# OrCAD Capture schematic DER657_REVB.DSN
size Custom
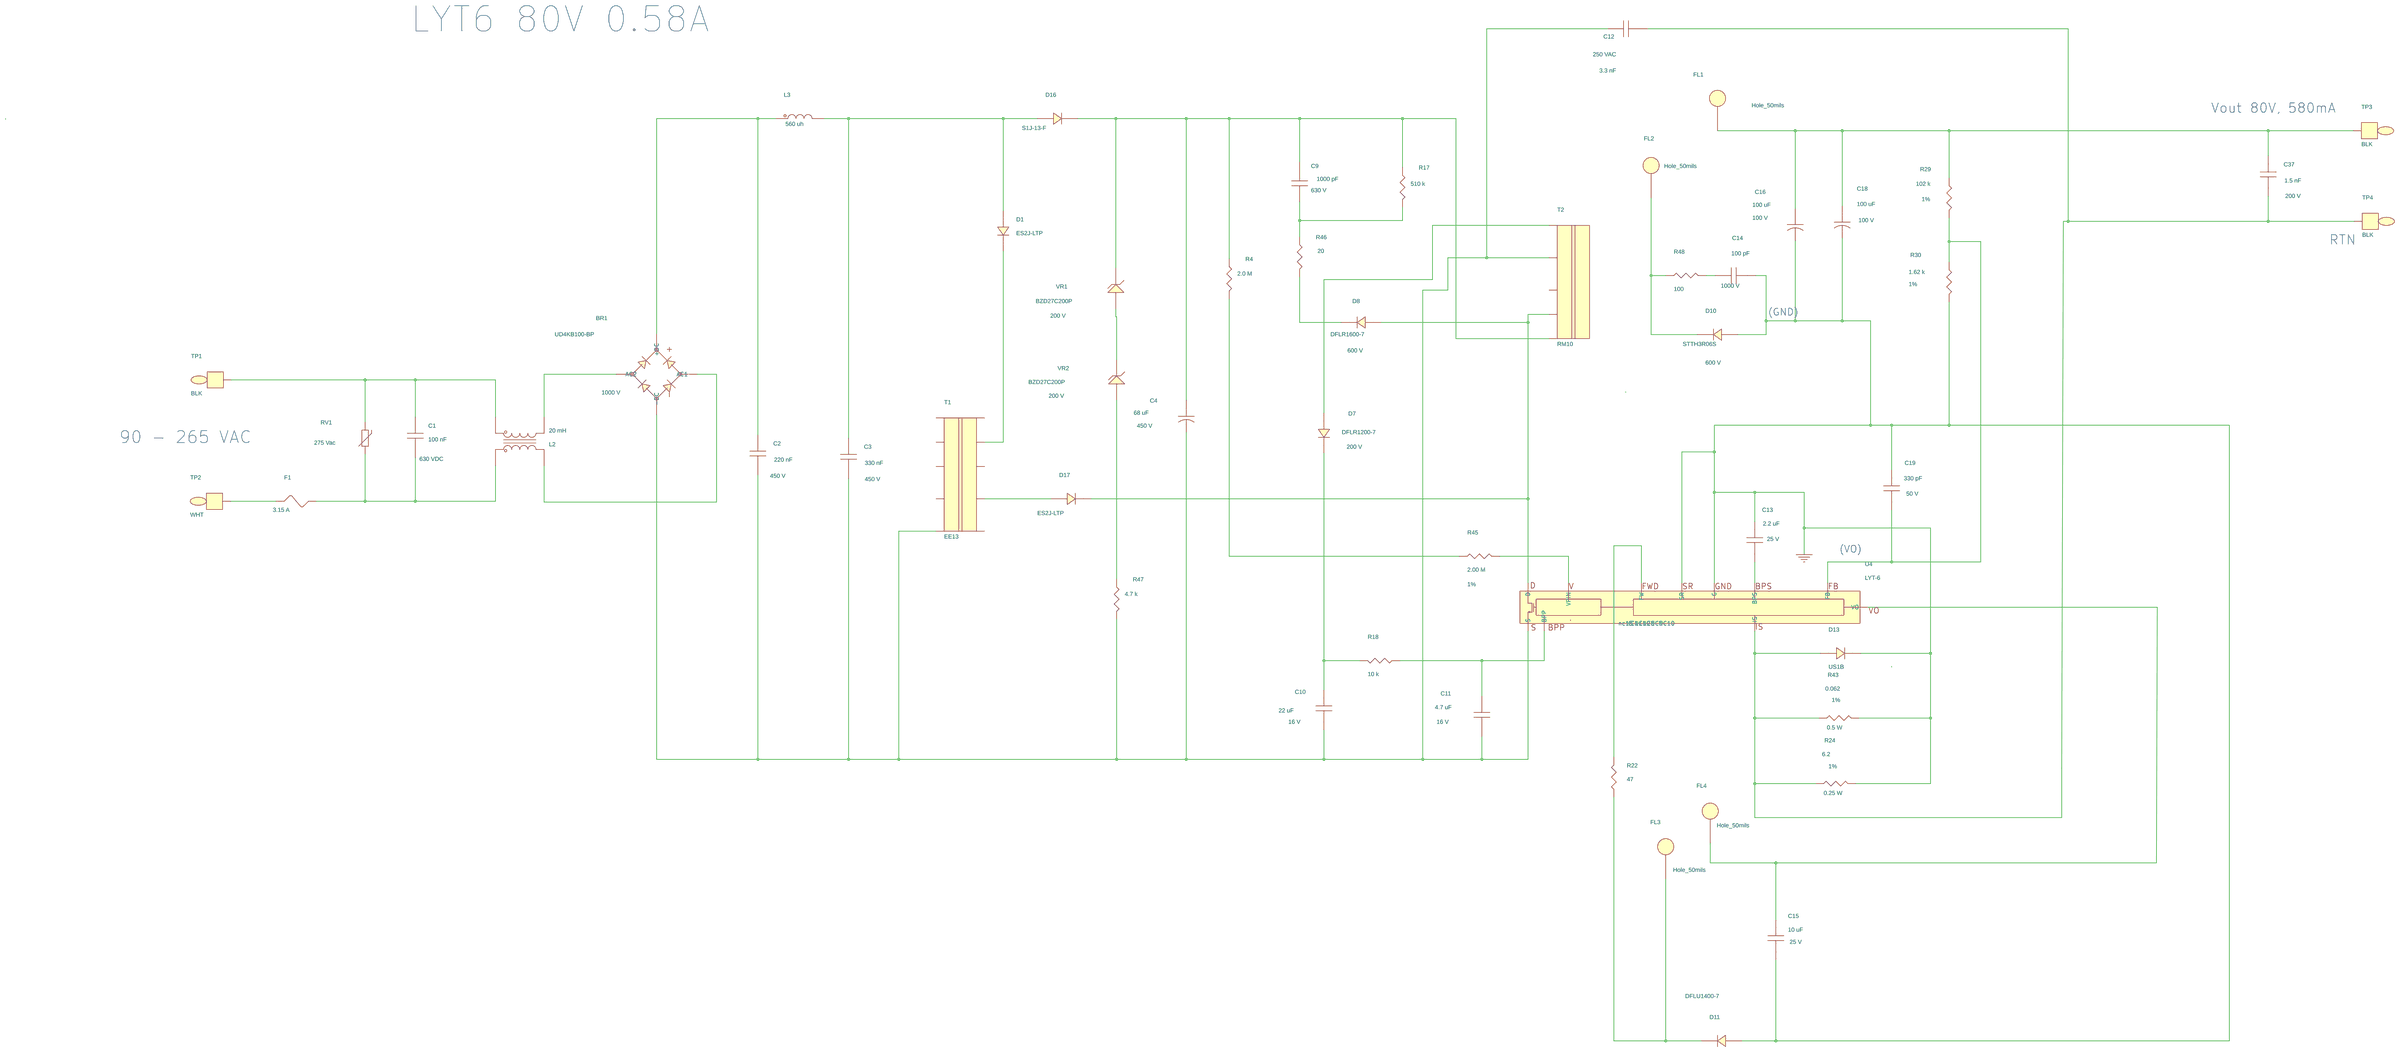
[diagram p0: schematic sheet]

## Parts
BR1  UD4KB100-BP  [pidaxbridgeD3K]
C1  100 nF  [pi_np_cap492x236ls394d040]
C2  220 nF  [pi_np_cap_rad470x220ls400d40]
C3  330 nF  [pi_np_caprad512x299ls394d040]
C4  68 uF  [pipolcapclyd630ls300040]
C9  1000 pF  [pismc1206]
C10  22 uF  [pismc1206]
C11  4.7 uF  [pismc0805]
C12  3.3 nF  [pinpycaprad540x290ls400040]
C13  2.2 uF  [pismc1206]
C14  100 pF  [pismc1206]
C15  10 uF  [pismc1206]
C16  100 uF  [pipolcapcyld400ls200040]
C18  100 uF  [pipolcapcyld400ls200040]
C19  330 pF  [pismc0603]
C37  1.5 nF  [pismc0805]
D1  ES2J-LTP  [pismdo214ac12]
D7  DFLR1200-7  [pismddflr120012]
D8  DFLR1600-7  [pismddflr120012]
D10  STTH3R06S  [pismdo214ab12]
D11  DFLU1400-7  [pismddflr120012]
D13  US1B  [pismdsma]
D16  S1J-13-F  [pismdsma]
D17  ES2J-LTP  [pismdo214ac12]
F1  3.15 A  [pi_rst_microfuse]
FL1  Hole_50mils  [pi_hole_50mil]
FL2  Hole_50mils  [pi_hole_50mil]
FL3  Hole_50mils  [pi_hole_50mil]
FL4  Hole_50mils  [pi_hole_50mil]
L2  20 mH  [piind4pKemetSS21V]
L3  560 uh  [pi_choke_RL5480-5_d2]
R4  2.0 M  [pi14wvresd100ls100d030]
R17  510 k  [pismr1206]
R18  10 k  [pismr1206]
R22  47  [pismr1206]
R24  6.2  [pismr1206]
R29  102 k  [pismr0805]
R30  1.62 k  [pismr0603]
R43  0.062  [pismr1206]
R45  2.00 M  [pismr1206]
R46  20  [pismr1206]
R47  4.7 k  [pismr1206]
R48  100  [pismr1210]
RV1  275 Vac  [pidisc500x225ls335x140040]
T1  EE13  [pi_bobbin_ee13v_10p]
T2  RM10  [pi_bobbin_rm10_5p]
TP1  BLK  [pitpkeystone125x125]
TP2  WHT  [pitpkeystone125x125]
TP3  BLK  [pitpkeystone125x125]
TP4  BLK  [pitpkeystone125x125]
U4  LYT-6  [pi_ic_insop_24d]
VR1  BZD27C200P  [pismdo219ab12]
VR2  BZD27C200P  [pismdo219ab12]

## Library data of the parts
BR1 = DISCRETE_BRIDGE_+~~-: ALT_SYMBOLS: pidaxbridgeD3K_horz; Disp_Voltage: 1000 V; FPLIST: pidaxbridgeD3K,pidaxbridgeD3K_horz; Part Number: 15-01213-00
C1 = CAP_NP: Disp_Voltage: 630 VDC; Part Number: 20-02095-00; Voltage: 630 VDC
C2 = CAP_NP: Disp_Voltage: 450 V; Part Number: 20-08691-00; Voltage: 450 V
C3 = CAP_NP: ALT_SYMBOLS: pi_np_caprad512x299ls394d040_h; Disp_Voltage: 450 V; FPLIST: pi_np_caprad512x299ls394d040,pi_np_caprad512x299ls394d040_h; Part Number: 20-00973-00; Voltage: 450 V
C4 = CAP_POL: ALT_SYMBOLS: pi_polcap_630ls300d40x1400_h; Disp_Voltage: 450 V; FPLIST: pipolcapclyd630ls300040,pi_polcap_630ls300d40x1400_h; PCB Editor PCBFP: pipolcapcyld250ls100030; Part Number: 20-01030-00; Tol: 20; Voltage: 450 V
C9 = CAP_NP: Disp_Voltage: 630 V; Part Number: 20-08616-00; Voltage: 630 V
C10 = CAP_NP: Disp_Voltage: 16 V; Part Number: 20-01038-00; Voltage: 16 V
C11 = CAP_NP: Disp_Voltage: 16 V; Part Number: 20-08947-00; Voltage: 16 V
C12 = CAP_NP: ALT_SYMBOLS: pinpycaprad540x290ls400040h; COMPGROUP: 3; Disp_Voltage: 250 VAC; FPLIST: pinpycaprad540x290ls400040,pinpycaprad540x290ls400040h; Part Number: 20-00377-00; Voltage: 250 VAC
C13 = CAP_NP: Disp_Voltage: 25 V; Part Number: 20-01034-00; Voltage: 25 V
C14 = CAP_NP: Disp_Voltage: 1000 V; PCB Editor PCBFP: pismc0603; Part Number: 20-00917-00; Voltage: 1000 V
C15 = CAP_NP: Disp_Voltage: 25 V; Part Number: 20-08608-00; Voltage: 25 V
C16 C18 = CAP_POL: ALT_SYMBOLS: pipolcapcyld400ls200040800h; COMPGROUP: 3; Disp_Voltage: 100 V; FPLIST: pipolcapcyld400ls200040,pipolcapcyld400ls200040800h; Part Number: 20-00954-00; Voltage: 100 V
C19 = CAP_NP: Disp_Voltage: 50 V; Part Number: 20-08676-00; Voltage: 50 V
C37 = CAP_NP: Disp_Voltage: 200 V; Part Number: 20-01150-00; Voltage: 200 V
D1 D17 = DIODE: COMPGROUP: 1; Part Number: 15-01076-00
D7 = DIODE: COMPGROUP: 1; Disp_Voltage: 200 V; Part Number: 15-01019-00
D8 = DIODE: Disp_Voltage: 600 V; Part Number: 15-00826-00
D10 = DIODE: Disp_Voltage: 600 V; Part Number: 15-00827-00
D11 = DIODE: Part Number: 15-00910-00
D13 = DIODE: Part Number: 15-00491-00
D16 = DIODE: COMPGROUP: 1; Part Number: 15-01034-00
F1 = FUSE: ALT_SYMBOLS: pirstmicrofusehoz; FPLIST: pi_rst_microfuse,pirstmicrofusehoz; Part Number: 40-00071-00; Voltage: 250 V
FL1-FL4 = FlyingLead: Part Number: 35-00283-00
L2 = INDUCTOR_4P_revF: Part Number: 30-00448-00
L3 = INDUCTOR_dot2: ALT_SYMBOLS: pi_choke_RL5480-5H_d2; FPLIST: pi_choke_RL5480-5_d2,pi_choke_RL5480-5H_d2; Part Number: 30-00317-00
R4 = R: ALT_SYMBOLS: pi14wvresd100ls200d030,pi14wresd100ls400d030,pi14wresd100ls500d030; FPLIST: pi14wvresd100ls100d030,pi14wvresd100ls200d030,pi14wresd100ls400d030,pi14wresd100ls500d030; Part Number: 05-03110-00
R17 = R: Part Number: 05-01417-00
R18 = R: Part Number: 05-01376-00
R22 = R: Part Number: 05-01320-00
R24 = R: ALT_SYMBOLS: pismr1206_1; Disp_Power: 0.25 W; Disp_Tol: 1%; FPLIST: pismr1206,pismr1206_1; Part Number: 05-06477-00
R29 = R: Disp_Tol: 1%; Part Number: 05-00781-00
R30 = R: Disp_Tol: 1%; Part Number: 05-01098-00
R43 = R: ALT_SYMBOLS: pismr1206_1; Disp_Power: 0.5 W; Disp_Tol: 1%; FPLIST: pismr1206,pismr1206_1; Part Number: 05-06487-00
R45 = R: Disp_Tol: 1%; Part Number: 05-03156-00
R46 = R: Part Number: 05-01311-00
R47 = R: Part Number: 05-01368-00
R48 = R: Disp_Power: 0.5 W; Part Number: 05-05428-00
RV1 = VARISTOR: FPLIST: pidisc500x225ls335x140040,pi_rad450x550ls300d040_h; Part Number: 85-00018-00
T1 = BEE13_10PINS_GENERIC: Part Number: 25-01023-00
T2 = BRM10_5P_GENERIC: ALT_SYMBOLS: pi_bobbin_rm10_5p_clp; FPLIST: pi_bobbin_rm10_5p,pi_bobbin_rm10_5p_clp; Part Number: 25-00921-00
TP1 TP3 TP4 = TESTPOINT: Part Number: 35-00042-00
TP2 = TESTPOINT: Part Number: 35-00044-00
U4 = DEV_Inno3CE: Part Number: 10-01035-00
VR1 VR2 = DIODE_ZENER: Disp_Voltage: 200 V; Part Number: 15-01184-00

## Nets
GND: C13.1 C14.2 C15.2 C16.2 C18.2 C19.1 D10.2 D11.2 D13.1 R24.2 R30.2 R43.2 U4.2(G) U4.5(SR)
NC8: U4.8(NC8)
NC9: U4.9(NC9)
NC10: U4.10(NC10)
NC11: U4.11(NC11)
NC12: U4.12(NC12)
NC15: U4.15(nc15)
N10967118: C10.1 D7.1 R18.1
N10967192: D8.1 R46.2
N10967208: D11.1 FL3.1 R22.1
N10967232: C15.1 FL4.1 U4.6(VO)
N10967272: D8.2 D17.1 T2.2 U4.24(D)
N10967292: C4.1 C9.2 D16.1 R4.1 R17.1 T2.1 VR1.1
N10967352: C11.1 R18.2 U4.14(BPP)
N10967360: C19.2 R29.2 R30.1 U4.3(FB)
N10967588: C16.1 C18.1 C37.1 FL1.1 R29.1 TP3.1
N10967612: C12.2 C37.2 D13.2 R24.1 R43.1 TP4.1 U4.1(IS)
N10967616: D10.1 FL2.1 R48.1
N10968210: C14.1 R48.2
N10968562: BR1.4(-DC) C2.2 C3.2 C4.2 C10.2 C11.2 C12.1 R47.2 T1.5 T2.4 U4.16(S)
N10970465: BR1.2(AC1) L2.4
N10970513: C1.2 F1.2 L2.2 RV1.1
N10971495: BR1.3(AC2) L2.3
N10975943: C9.1 R17.2 R46.1
N11160740: D7.2 T2.5
N11207739: C1.1 L2.1 RV1.2 TP1.1
N11231482: R22.2 U4.7(FW)
N11317958: R45.2 U4.13(VPIN)
N11319179: C13.2 U4.4(BPS)
N11446006: D1.1 T1.9
N11450999: C3.1 D1.2 D16.2 L3.1
N11451346: R4.2 R45.1
N11459929: BR1.1(+DC) C2.1 L3.2
N11463653: D17.2 T1.7
N11465077: F1.1 TP2.1
N11473887: VR1.2 VR2.1
N11473996: R47.1 VR2.2

Not connected (* = marked no-connect by the designer): T1 1 2 3 4 6 8 10; T2 3

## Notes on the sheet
- LYT6 80V 0.58A
- Vout
- 80V, 580mA
- RTN
- (GND)
- 90 - 265 VAC
- (VO)
